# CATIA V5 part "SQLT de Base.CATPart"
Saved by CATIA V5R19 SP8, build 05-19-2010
Part number: SQLT de Base
Publications: "Point.A", "Point.B", "Point.C", "Point.D", "Point.E", "Point.F"
Bounding box of the stored display mesh (mm): x 0 to 0, y -1250 to 2700, z -2650 to 3600
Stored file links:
  C:\Users\ThinkMotion\Desktop\EU_thinkMotion\iao\IAO_MMS_Groupe3\fovide\fovide\SQLT de Base.CATPart
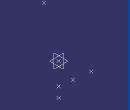
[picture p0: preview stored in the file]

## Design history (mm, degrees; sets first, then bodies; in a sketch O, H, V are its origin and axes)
Set1 "set de base"
  Point1 "Point.A": (0, 2700, 600)
  Point2 "Point.B": (0, 1200, -750)
  Point3 "Point.C": (0, 0, -1800)
  Point4 "Point.D": (0, 0, 0)
  Point5 "Point.E": (0, -1250, 3600)
  Point6 "Point.F": (0, 0, -2650)
Body1 (main body)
